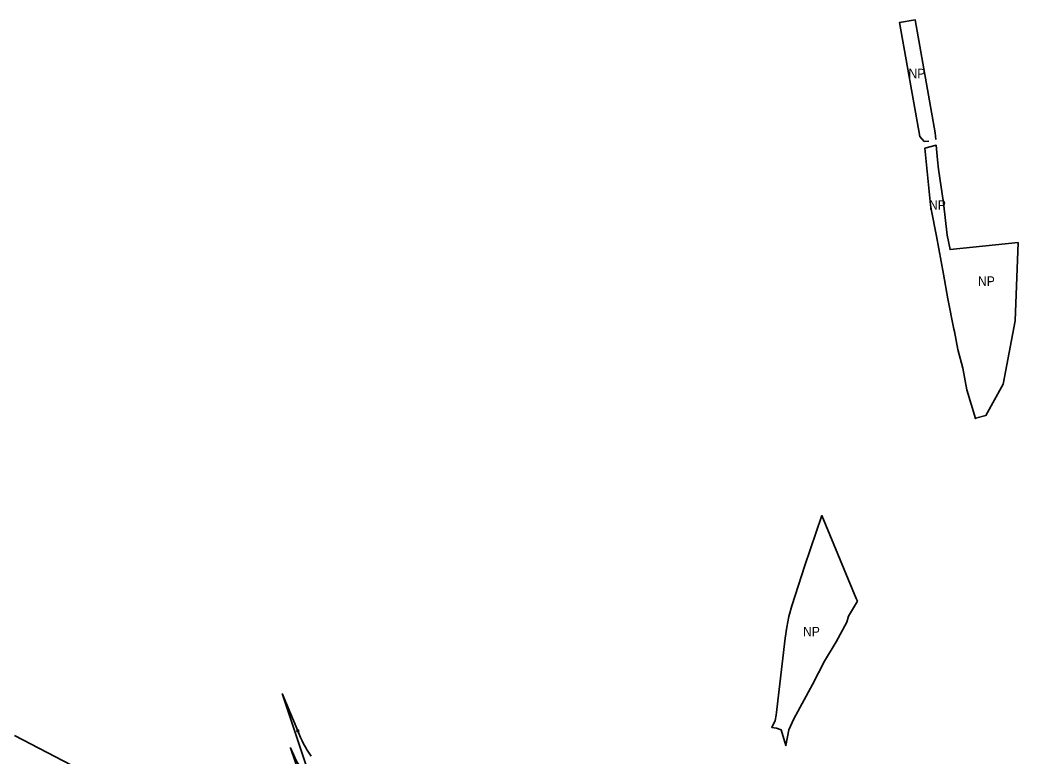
# Model space of a CAD drawing. Extents: x -650276 to -642489, y -1074311 to -1066658.
# Drawn here: x -646929 to -645670, y -1068433 to -1067504 of the extents above; entities that cross this region are included whole.
import ezdxf

# ---------------------------------------------------------------- set-up
doc = ezdxf.new("R2010")
doc.units = 0
doc.header["$LTSCALE"] = 4.8
doc.header["$PDMODE"] = 32
doc.header["$PDSIZE"] = 2.4
for name, color, linetype, lineweight in [('24', 7, 'Continuous', 35), ('42', 7, 'Continuous', 35), ('48', 7, 'Continuous', 35)]:
    doc.layers.add(name, color=color, linetype=linetype, lineweight=lineweight)
doc.layers.add('62', color=7, linetype='Continuous')

msp = doc.modelspace()

# ---------------------------------------------------------------- linework, layer by layer
at = {"layer": '24'}
msp.add_line((-646578.881, -1068401.54), (-646598.635, -1068354.436), dxfattribs=at)
msp.add_line((-646578.881, -1068401.54), (-646598.635, -1068354.436), dxfattribs=at)
for points in [[(-646598.635, -1068354.436), (-646579.62, -1068411.29), (-646564.78, -1068455.41), (-646561.544, -1068464.842)], [(-646598.635, -1068354.436), (-646579.62, -1068411.29), (-646564.78, -1068455.41), (-646561.544, -1068464.842)], [(-646864.48, -1068444.64), (-646936.47, -1068407.23)]]:
    msp.add_lwpolyline(points, dxfattribs=at)
for start in [200.6496, 200.64975]:
    msp.add_arc((-646447.332, -1068351.964), 140.58, start, 215.36619, dxfattribs=at)
msp.add_point((-646578.881, -1068401.54), dxfattribs=at)
at = {"layer": '42'}
msp.add_lwpolyline([(-646561.544, -1068464.842), (-646572.984, -1068451.81), (-646580.625, -1068439.803), (-646588.07, -1068422.96), (-646576.4, -1068457.27), (-646568.87, -1068479.14), (-646556.22, -1068515.84), (-646545.57, -1068511.42), (-646537.71, -1068508.16)], dxfattribs=at)
at = {"layer": '48'}
for points in [[(-645773.771, -1067655.463), (-645774.48, -1067646.99), (-645799.72, -1067504.47), (-645819.48, -1067507.57), (-645793.94, -1067651.61)], [(-645793.94, -1067651.61), (-645788.395, -1067658.038), (-645782.72, -1067657.28)], [(-645872.64, -1068238.08), (-645874.15, -1068234.44), (-645917.44, -1068129.99), (-645938.87, -1068193.06)], [(-645938.87, -1068193.06), (-645951.35, -1068230.61), (-645955.63, -1068243.79), (-645959.15, -1068257.17), (-645961.93, -1068270.74), (-645963.94, -1068284.44), (-645975.46, -1068381.74), (-645976.72, -1068388.53), (-645980.61, -1068397.35), (-645974.67, -1068398.28), (-645968.86, -1068400.15), (-645962.86, -1068420.15), (-645959.41, -1068400.16), (-645952.92, -1068386.53), (-645929.29, -1068342.91), (-645914.12, -1068313.54), (-645899.73, -1068289.25), (-645886.28, -1068264.22), (-645883.87, -1068256.88), (-645872.64, -1068238.08)]]:
    msp.add_lwpolyline(points, dxfattribs=at)
msp.add_lwpolyline([(-645750.41, -1067897.81), (-645745.86, -1067920.32), (-645739.85, -1067943.75), (-645734.61, -1067971.28), (-645723.73, -1068007.49), (-645723.785, -1068007.069), (-645710.519, -1068003.601), (-645688.88, -1067964.087), (-645673.827, -1067884.119), (-645670.064, -1067785.335), (-645755.758, -1067794.254), (-645759.32, -1067775.89), (-645763.92, -1067735.14), (-645770.39, -1067692.63), (-645771.86, -1067680.92), (-645773.23, -1067662.67), (-645787.55, -1067666.46), (-645780.39, -1067737.84), (-645779.64, -1067743.41), (-645773.04, -1067777.35), (-645764.11, -1067825.26), (-645758.47, -1067856.55), (-645751.08, -1067894.5)], close=True, dxfattribs=at)

# ---------------------------------------------------------------- texts
at = {"layer": '62', "width": 0.95}
for p in [(-645808.298, -1067578), (-645782.298, -1067744), (-645720.583, -1067840.041), (-645941.298, -1068282.326)]:
    msp.add_text('NP', height=12, dxfattribs=at).set_placement(p)

doc.saveas('drawing.dxf')
